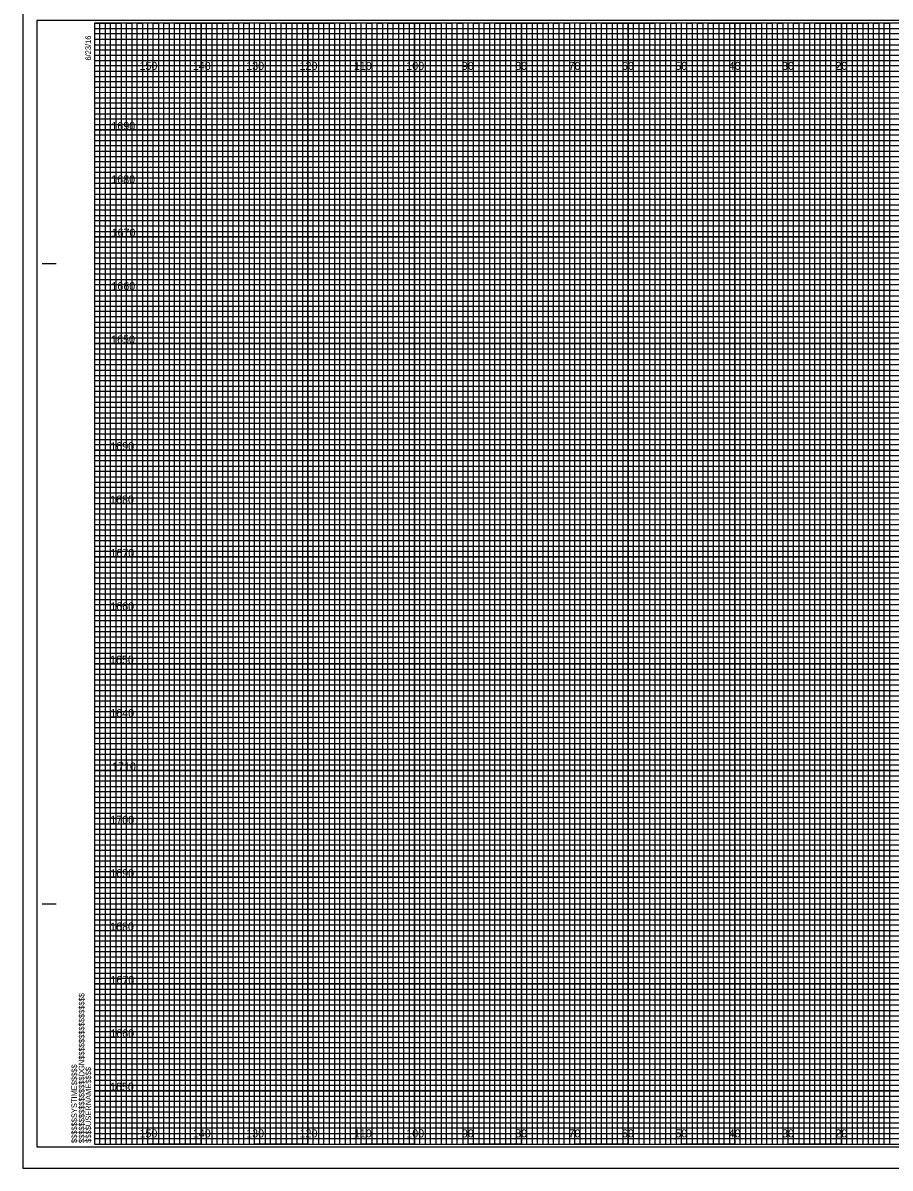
# Model space of a CAD drawing. Extents: x 1443 to 2205, y -29 to 5484.
# Drawn here: x 1443.3 to 1605.8, y 645.2 to 859.8 of the extents above; entities that cross this region are included whole.
import ezdxf

# ---------------------------------------------------------------- set-up
doc = ezdxf.new("R2010")
doc.units = 0
for name, color, linetype in [('Pattern 3', 7, 'Continuous'), ('Prop Retaining Wall', 7, 'Continuous'), ('Prop XS DDE Earthwork Shape', 7, 'Continuous'), ('Prop XS DDE Slope Text', 7, 'Continuous'), ('Prop XS DDE Text', 7, 'Continuous'), ('Prop XS Earthwork Shape', 7, 'Continuous'), ('Prop XS Retaining Wall', 7, 'Continuous'), ('Prop XS Station Labels', 7, 'Continuous'), ('Prop XS Temporary Shoring', 7, 'Continuous'), ('Raster_Level_0', 7, 'Continuous'), ('Scratch_Level_3', 7, 'Continuous')]:
    doc.layers.add(name, color=color, linetype=linetype)

msp = doc.modelspace()

# ---------------------------------------------------------------- linework, layer by layer
at = {"layer": 'Pattern 3'}
for p, q in [((1443.28, 864.21), (1443.28, 645.21)), ((1443.28, 645.21), (1779.98, 645.21))]:
    msp.add_line(p, q, dxfattribs=at)
at = {"layer": 'Prop Retaining Wall'}
for p, q in [((1456.68, 858.71), (1716.68, 858.71)), ((1716.68, 857.69), (1456.68, 857.69)), ((1456.68, 857.69), (1456.68, 856.71)), ((1456.68, 856.71), (1716.68, 856.71)), ((1716.68, 855.6), (1456.68, 855.6)), ((1456.68, 855.6), (1456.68, 853.71)), ((1456.68, 853.71), (1776.68, 853.71))]:
    msp.add_line(p, q, dxfattribs=at)
for points in [[(1456.68, 852.71), (1726.68, 852.71), (1776.68, 852.71), (1776.68, 851.71), (1456.68, 851.71)], [(1456.68, 850.71), (1776.68, 850.71), (1776.68, 848.71), (1456.68, 848.71)], [(1456.68, 847.71), (1776.68, 847.71), (1776.68, 846.71), (1456.68, 846.69)], [(1456.68, 845.71), (1776.68, 845.71), (1776.68, 843.71), (1456.68, 843.71)], [(1456.68, 842.71), (1776.68, 842.71), (1776.68, 841.71), (1456.68, 841.71)], [(1456.68, 840.71), (1776.68, 840.71), (1776.68, 838.71), (1456.68, 838.71)], [(1456.68, 837.71), (1776.68, 837.71), (1776.68, 836.71), (1456.68, 836.71)], [(1456.68, 835.71), (1776.68, 835.71), (1776.68, 833.71), (1456.68, 833.71)], [(1456.68, 832.71), (1776.68, 832.71), (1776.68, 831.71), (1456.68, 831.71)], [(1456.68, 830.71), (1776.68, 830.71), (1776.68, 828.71), (1456.68, 828.71)], [(1456.68, 827.71), (1776.68, 827.71), (1776.68, 826.71), (1456.68, 826.71)], [(1456.68, 825.71), (1776.68, 825.71), (1776.68, 823.66), (1776.68, 822.71), (1776.68, 821.71), (1456.68, 821.71)], [(1456.68, 823.71), (1776.68, 823.71), (1776.68, 822.71), (1456.68, 822.71)], [(1456.68, 820.71), (1776.68, 820.71), (1776.68, 818.71), (1456.68, 818.74)], [(1456.68, 818.74), (1776.68, 818.71), (1776.68, 817.71), (1456.68, 817.71)], [(1456.68, 816.71), (1776.68, 816.71), (1776.68, 815.71), (1456.68, 815.71)], [(1456.68, 813.71), (1776.68, 813.71), (1776.68, 812.71), (1456.68, 812.71)], [(1456.68, 811.71), (1776.68, 811.71), (1776.68, 810.71), (1456.68, 810.71)], [(1456.61, 808.6), (1776.68, 808.6), (1776.68, 807.59), (1456.61, 807.59)], [(1456.68, 806.71), (1776.68, 806.71), (1776.68, 805.71), (1456.68, 805.71)], [(1456.68, 803.71), (1776.68, 803.71), (1776.68, 802.71), (1456.68, 802.71)], [(1456.68, 801.71), (1776.68, 801.71), (1776.68, 800.71), (1456.68, 800.71)], [(1456.68, 798.71), (1776.68, 798.71), (1776.68, 797.71), (1456.68, 797.71)], [(1456.68, 796.71), (1776.68, 796.71), (1776.68, 795.71), (1456.68, 795.71)], [(1456.68, 793.71), (1776.68, 793.71), (1776.68, 792.71), (1456.68, 792.71)], [(1456.68, 791.71), (1776.68, 791.71), (1776.68, 790.71), (1456.68, 790.71)], [(1456.68, 788.71), (1776.68, 788.71), (1776.67, 787.69), (1456.68, 787.71)], [(1456.68, 786.71), (1776.68, 786.71), (1776.68, 785.71), (1456.68, 785.71)], [(1456.68, 783.71), (1776.68, 783.71), (1776.68, 782.71), (1456.68, 782.71)], [(1456.68, 781.71), (1776.68, 781.71), (1776.68, 780.71), (1456.68, 780.71)], [(1456.68, 778.71), (1776.68, 778.71), (1776.68, 777.71), (1456.68, 777.71)], [(1456.68, 776.71), (1776.68, 776.71), (1776.68, 775.71), (1456.68, 775.71)], [(1456.68, 773.71), (1776.68, 773.71), (1776.68, 772.71), (1456.68, 772.71)], [(1456.68, 771.71), (1776.68, 771.71), (1776.68, 770.71), (1456.68, 770.71)], [(1456.68, 768.71), (1776.68, 768.71), (1776.68, 767.71), (1456.68, 767.71)], [(1456.68, 766.7), (1776.75, 766.62), (1776.68, 765.71), (1456.68, 765.71)], [(1456.68, 763.71), (1776.68, 763.71), (1776.68, 762.71), (1456.68, 762.71)], [(1456.68, 761.71), (1776.68, 761.71), (1776.68, 760.71), (1456.68, 760.71)], [(1456.68, 758.71), (1776.68, 758.71), (1776.68, 757.71), (1456.68, 757.71)], [(1456.68, 756.71), (1776.68, 756.71), (1776.68, 755.71), (1456.68, 755.71)], [(1456.68, 753.71), (1776.68, 753.71), (1776.68, 752.71), (1456.68, 752.71)], [(1456.68, 751.71), (1776.68, 751.71), (1776.68, 750.71), (1456.68, 750.71)], [(1456.68, 748.71), (1776.68, 748.71), (1776.68, 747.71), (1456.68, 747.71)], [(1456.68, 746.71), (1776.68, 746.71), (1776.68, 745.71), (1456.68, 745.71)], [(1456.68, 743.71), (1776.68, 743.71), (1776.68, 742.71), (1456.68, 742.71)], [(1456.68, 741.71), (1776.68, 741.71), (1776.68, 740.71), (1456.68, 740.71)], [(1456.68, 738.71), (1776.68, 738.71), (1776.68, 737.71), (1456.68, 737.71)], [(1456.68, 736.71), (1776.68, 736.71), (1776.68, 735.71), (1456.68, 735.71)], [(1456.68, 733.71), (1776.68, 733.71), (1776.68, 732.71), (1456.68, 732.71)], [(1456.68, 731.71), (1776.68, 731.71), (1776.68, 730.71), (1456.68, 730.71)], [(1456.68, 728.71), (1776.68, 728.71), (1776.67, 727.69), (1456.68, 727.71)], [(1456.68, 726.71), (1776.68, 726.71), (1776.68, 725.71), (1456.68, 725.71)], [(1456.68, 723.71), (1776.68, 723.71), (1776.68, 722.71), (1456.68, 722.71)], [(1456.68, 721.71), (1776.68, 721.71), (1776.68, 720.71), (1456.68, 720.71)], [(1456.68, 718.71), (1776.68, 718.71), (1776.68, 717.71), (1456.68, 717.71)], [(1456.68, 716.71), (1776.68, 716.71), (1776.68, 715.71), (1456.68, 715.71)], [(1456.68, 713.71), (1776.68, 713.71), (1776.68, 712.71), (1456.68, 712.71)], [(1456.68, 711.71), (1776.68, 711.71), (1776.68, 710.71), (1456.68, 710.71)], [(1456.68, 708.71), (1776.68, 708.71), (1776.68, 707.71), (1456.68, 707.71)], [(1456.68, 706.7), (1776.75, 706.62), (1776.68, 705.71), (1456.68, 705.71)], [(1456.68, 703.71), (1776.68, 703.71), (1776.68, 702.71), (1456.68, 702.71)], [(1456.68, 701.71), (1776.68, 701.71), (1776.68, 700.71), (1456.68, 700.71)], [(1456.68, 698.71), (1776.68, 698.71), (1776.68, 697.71), (1456.68, 697.71)], [(1456.68, 696.71), (1776.68, 696.71), (1776.68, 695.71), (1456.68, 695.71)], [(1456.68, 693.71), (1776.68, 693.71), (1776.68, 692.71), (1456.68, 692.71)], [(1456.68, 691.71), (1776.68, 691.71), (1776.68, 690.71), (1456.68, 690.71)], [(1456.68, 688.71), (1776.68, 688.71), (1776.68, 687.71), (1456.68, 687.71)], [(1456.68, 686.71), (1776.68, 686.71), (1776.68, 685.71), (1456.68, 685.71)], [(1456.68, 683.71), (1776.68, 683.71), (1776.68, 682.71), (1456.68, 682.71)], [(1456.68, 681.71), (1776.68, 681.71), (1776.68, 680.71), (1456.68, 680.71)], [(1456.68, 678.71), (1776.68, 678.71), (1776.68, 677.71), (1456.68, 677.71)], [(1456.68, 676.71), (1776.68, 676.71), (1776.68, 675.71), (1456.68, 675.71)], [(1456.68, 673.71), (1776.68, 673.71), (1776.68, 672.71), (1456.68, 672.71)], [(1456.68, 671.71), (1776.68, 671.71), (1776.68, 670.71), (1456.68, 670.71)], [(1456.68, 668.71), (1776.68, 668.71), (1776.68, 667.71), (1456.68, 667.71)], [(1456.68, 666.71), (1776.68, 666.71), (1776.68, 665.71), (1456.68, 665.71)], [(1456.68, 663.71), (1776.68, 663.71), (1776.68, 662.71), (1456.68, 662.71)], [(1456.68, 661.71), (1776.68, 661.71), (1776.68, 660.71), (1456.68, 660.71)], [(1456.68, 658.71), (1776.68, 658.71), (1776.68, 657.71), (1456.68, 657.71)], [(1456.68, 656.71), (1776.68, 656.71), (1776.68, 655.71), (1456.68, 655.71)], [(1456.68, 653.71), (1776.68, 653.71), (1776.68, 652.71), (1456.68, 652.71)], [(1456.68, 651.71), (1776.68, 651.71), (1776.68, 650.71), (1456.68, 650.71)]]:
    msp.add_lwpolyline(points, dxfattribs=at)
at = {"layer": 'Prop XS DDE Earthwork Shape'}
msp.add_lwpolyline([(1445.88, 649.21), (1779.08, 649.21), (1779.08, 860.21), (1445.88, 860.21)], close=True, dxfattribs=at)
at = {"layer": 'Prop XS DDE Slope Text'}
for points in [[(1456.68, 649.71), (1457.68, 649.71), (1457.68, 859.71), (1458.68, 859.71), (1458.68, 649.71)], [(1458.68, 649.71), (1459.68, 649.71), (1459.68, 859.71), (1460.68, 859.71), (1460.68, 649.71)], [(1461.68, 649.71), (1462.68, 649.71), (1462.68, 859.71), (1463.68, 859.71), (1463.68, 649.71)], [(1463.68, 649.71), (1464.68, 649.71), (1464.68, 859.71), (1465.68, 859.71), (1465.68, 649.71)], [(1466.68, 649.71), (1467.68, 649.71), (1467.68, 859.71), (1468.68, 859.71), (1468.68, 649.71)], [(1468.68, 649.71), (1469.68, 649.71), (1469.68, 859.71), (1470.68, 859.71), (1470.68, 649.71)], [(1471.68, 649.71), (1472.68, 649.71), (1472.68, 859.71), (1473.68, 859.71), (1473.68, 649.71)], [(1473.68, 649.71), (1474.68, 649.71), (1474.68, 859.71), (1475.68, 859.71), (1475.68, 649.71)], [(1476.68, 649.71), (1477.68, 649.71), (1477.68, 859.71), (1478.68, 859.71), (1478.68, 649.71)], [(1478.68, 649.71), (1479.68, 649.71), (1479.68, 859.71), (1480.68, 859.71), (1480.68, 649.71)], [(1481.68, 649.71), (1482.68, 649.71), (1482.68, 859.71), (1483.68, 859.71), (1483.68, 649.71)], [(1483.68, 649.71), (1484.68, 649.71), (1484.68, 859.71), (1485.68, 859.71), (1485.68, 649.71)], [(1486.68, 649.71), (1487.68, 649.71), (1487.68, 859.71), (1488.68, 859.71), (1488.68, 649.71)], [(1488.68, 649.71), (1489.68, 649.71), (1489.68, 859.71), (1490.68, 859.71), (1490.68, 649.71)], [(1491.68, 649.71), (1492.68, 649.71), (1492.68, 859.71), (1493.68, 859.71), (1493.68, 649.71)], [(1493.68, 649.71), (1494.68, 649.71), (1494.68, 859.71), (1495.68, 859.71), (1495.68, 649.71)], [(1496.68, 649.71), (1497.68, 649.71), (1497.68, 859.71), (1498.68, 859.71), (1498.68, 649.71)], [(1498.68, 649.71), (1499.68, 649.71), (1499.68, 859.71), (1500.68, 859.71), (1500.68, 649.71)], [(1501.68, 649.71), (1502.68, 649.71), (1502.68, 859.71), (1503.68, 859.71), (1503.68, 649.71)], [(1503.68, 649.71), (1504.68, 649.71), (1504.68, 859.71), (1505.68, 859.71), (1505.68, 649.71)], [(1506.68, 649.71), (1507.68, 649.71), (1507.68, 859.71), (1508.68, 859.71), (1508.68, 649.71)], [(1508.68, 649.71), (1509.68, 649.71), (1509.68, 859.71), (1510.68, 859.71), (1510.68, 649.71)], [(1511.68, 649.71), (1512.68, 649.71), (1512.68, 859.71), (1513.68, 859.71), (1513.68, 649.71)], [(1513.68, 649.71), (1514.68, 649.71), (1514.68, 859.71), (1515.68, 859.71), (1515.68, 649.71)], [(1516.68, 649.71), (1517.68, 649.71), (1517.68, 859.71), (1518.68, 859.71), (1518.68, 649.71)], [(1518.68, 649.71), (1519.68, 649.71), (1519.68, 859.71), (1520.68, 859.71), (1520.68, 649.71)], [(1521.68, 649.71), (1522.68, 649.71), (1522.68, 859.71), (1523.68, 859.71), (1523.68, 649.71)], [(1523.68, 649.71), (1524.68, 649.71), (1524.68, 859.71), (1525.68, 859.71), (1525.68, 649.71)], [(1526.68, 649.71), (1527.68, 649.71), (1527.68, 859.71), (1528.68, 859.71), (1528.68, 649.71)], [(1528.68, 649.71), (1529.68, 649.71), (1529.68, 859.71), (1530.68, 859.71), (1530.68, 649.71)], [(1531.68, 649.71), (1532.68, 649.71), (1532.68, 859.71), (1533.68, 859.71), (1533.68, 649.71)], [(1533.68, 649.71), (1534.68, 649.71), (1534.68, 859.71), (1535.68, 859.71), (1535.68, 649.71)], [(1536.68, 649.71), (1537.68, 649.71), (1537.68, 859.71), (1538.68, 859.71), (1538.68, 649.71)], [(1538.68, 649.71), (1539.68, 649.71), (1539.68, 859.71), (1540.68, 859.71), (1540.68, 649.71)], [(1541.68, 649.71), (1542.68, 649.71), (1542.68, 859.71), (1543.68, 859.71), (1543.68, 649.71)], [(1543.68, 649.71), (1544.68, 649.71), (1544.68, 859.71), (1545.68, 859.71), (1545.68, 649.71)], [(1546.68, 649.71), (1547.68, 649.71), (1547.68, 859.71), (1548.68, 859.71), (1548.68, 649.71)], [(1548.68, 649.71), (1549.68, 649.71), (1549.68, 859.71), (1550.68, 859.71), (1550.68, 649.71)], [(1551.68, 649.71), (1552.68, 649.71), (1552.68, 859.71), (1553.68, 859.71), (1553.68, 649.71)], [(1553.68, 649.71), (1554.68, 649.71), (1554.68, 859.71), (1555.68, 859.71), (1555.68, 649.71)], [(1556.68, 649.71), (1557.68, 649.71), (1557.68, 859.71), (1558.68, 859.71), (1558.68, 649.71)], [(1558.68, 649.71), (1559.68, 649.71), (1559.68, 859.71), (1560.68, 859.71), (1560.68, 649.71)], [(1561.68, 649.71), (1562.68, 649.71), (1562.68, 859.71), (1563.68, 859.71), (1563.68, 649.71)], [(1563.68, 649.71), (1564.68, 649.71), (1564.68, 859.71), (1565.68, 859.71), (1565.68, 649.71)], [(1566.68, 649.71), (1567.68, 649.71), (1567.68, 859.71), (1568.68, 859.71), (1568.68, 649.71)], [(1568.68, 649.71), (1569.68, 649.71), (1569.68, 859.71), (1570.68, 859.71), (1570.68, 649.71)], [(1571.68, 649.71), (1572.68, 649.71), (1572.68, 859.71), (1573.68, 859.71), (1573.68, 649.71)], [(1573.68, 649.71), (1574.68, 649.71), (1574.68, 859.71), (1575.68, 859.71), (1575.68, 649.71)], [(1576.68, 649.71), (1577.68, 649.71), (1577.68, 859.71), (1578.68, 859.71), (1578.68, 649.71)], [(1578.68, 649.71), (1579.68, 649.71), (1579.68, 859.71), (1580.68, 859.71), (1580.68, 649.71)], [(1581.68, 649.71), (1582.68, 649.71), (1582.68, 859.71), (1583.68, 859.71), (1583.68, 649.71)], [(1583.68, 649.71), (1584.68, 649.71), (1584.68, 859.71), (1585.68, 859.71), (1585.68, 649.71)], [(1586.68, 649.71), (1587.68, 649.71), (1587.68, 859.71), (1588.68, 859.71), (1588.68, 649.71)], [(1588.68, 649.71), (1589.68, 649.71), (1589.68, 859.71), (1590.68, 859.71), (1590.68, 649.71)], [(1591.68, 649.71), (1592.68, 649.71), (1592.68, 859.71), (1593.68, 859.71), (1593.68, 649.71)], [(1593.68, 649.71), (1594.68, 649.71), (1594.68, 859.71), (1595.68, 859.71), (1595.68, 649.71)], [(1596.68, 649.71), (1597.68, 649.71), (1597.68, 859.71), (1598.68, 859.71), (1598.68, 649.71)], [(1598.68, 649.71), (1599.68, 649.71), (1599.68, 859.71), (1600.68, 859.71), (1600.68, 649.71)], [(1601.68, 649.71), (1602.68, 649.71), (1602.68, 859.71), (1603.68, 859.71), (1603.68, 649.71)], [(1603.68, 649.71), (1604.68, 649.71), (1604.68, 859.71), (1605.68, 859.71), (1605.68, 649.71)]]:
    msp.add_lwpolyline(points, dxfattribs=at)
at = {"layer": 'Prop XS DDE Text'}
msp.add_lwpolyline([(1443.28, 645.21), (1779.98, 645.21), (1779.98, 864.21), (1443.28, 864.21)], close=True, dxfattribs=at)
at = {"layer": 'Prop XS Earthwork Shape'}
for p, q in [((1466.68, 859.71), (1456.68, 859.71)), ((1466.68, 649.71), (1466.68, 859.71)), ((1486.68, 859.71), (1476.68, 859.71)), ((1476.68, 859.71), (1476.68, 649.71)), ((1486.68, 649.71), (1486.68, 859.71)), ((1506.68, 859.71), (1496.68, 859.71)), ((1496.68, 859.71), (1496.68, 649.71)), ((1506.68, 649.71), (1506.68, 859.71)), ((1526.68, 859.71), (1516.68, 859.71)), ((1516.68, 859.71), (1516.68, 649.71)), ((1526.68, 649.71), (1526.68, 859.71)), ((1546.68, 859.71), (1536.68, 859.71)), ((1536.68, 859.71), (1536.68, 649.71)), ((1546.68, 649.71), (1546.68, 859.71)), ((1566.68, 859.71), (1556.68, 859.71)), ((1556.68, 859.71), (1556.68, 649.71)), ((1566.68, 649.71), (1566.68, 859.71)), ((1586.68, 859.71), (1576.68, 859.71)), ((1576.68, 859.71), (1576.68, 649.71)), ((1586.68, 649.71), (1586.68, 859.71)), ((1606.68, 859.71), (1596.68, 859.71)), ((1596.68, 859.71), (1596.68, 649.71)), ((1476.68, 649.71), (1466.68, 649.71)), ((1496.68, 649.71), (1486.68, 649.71)), ((1516.68, 649.71), (1506.68, 649.71)), ((1536.68, 649.71), (1526.68, 649.71)), ((1556.68, 649.71), (1546.68, 649.71)), ((1576.68, 649.71), (1566.68, 649.71)), ((1596.68, 649.71), (1586.68, 649.71))]:
    msp.add_line(p, q, dxfattribs=at)
for points in [[(1456.68, 849.71), (1776.68, 849.71), (1776.68, 839.71), (1456.68, 839.71)], [(1456.68, 829.71), (1776.68, 829.71), (1776.68, 819.71), (1456.68, 819.71)], [(1456.68, 809.71), (1776.68, 809.71), (1776.68, 799.71), (1456.68, 799.71)], [(1456.68, 789.71), (1776.68, 789.71), (1776.68, 779.71), (1456.68, 779.71)], [(1456.68, 769.71), (1776.68, 769.71), (1776.68, 759.71), (1456.68, 759.71)], [(1456.68, 749.71), (1776.68, 749.71), (1776.68, 739.71), (1456.68, 739.71)], [(1456.68, 729.71), (1776.68, 729.71), (1776.68, 719.71), (1456.68, 719.71)], [(1456.68, 709.71), (1776.68, 709.71), (1776.68, 699.71), (1456.68, 699.71)], [(1456.68, 689.71), (1776.68, 689.71), (1776.68, 679.71), (1456.68, 679.71)], [(1456.68, 669.71), (1776.68, 669.71), (1776.68, 659.71), (1456.68, 659.71)]]:
    msp.add_lwpolyline(points, dxfattribs=at)
at = {"layer": 'Prop XS Retaining Wall'}
for p, q in [((1446.88, 814.71), (1449.38, 814.71)), ((1446.98, 814.71), (1449.48, 814.71)), ((1446.88, 694.71), (1449.38, 694.71)), ((1446.98, 694.71), (1449.48, 694.71)), ((1456.68, 649.71), (1456.68, 649.71)), ((1456.68, 649.71), (1456.68, 649.71)), ((1456.68, 649.71), (1456.68, 649.71)), ((1456.68, 649.71), (1456.68, 649.71)), ((1456.68, 649.71), (1456.68, 649.71)), ((1456.68, 649.71), (1456.68, 649.71)), ((1456.68, 649.71), (1456.68, 649.71))]:
    msp.add_line(p, q, dxfattribs=at)
msp.add_lwpolyline([(1776.68, 859.71), (1456.68, 859.71), (1456.68, 649.71), (1776.68, 649.71)], close=True, dxfattribs=at)
at = {"layer": 'Prop XS Station Labels'}
for points in [[(1456.68, 859.71), (1461.68, 859.71), (1461.68, 649.71), (1471.68, 649.71), (1471.68, 859.71), (1481.68, 859.71), (1481.68, 649.71), (1491.68, 649.71), (1491.68, 859.71), (1501.68, 859.71), (1501.68, 649.71), (1511.68, 649.71), (1511.68, 859.71), (1521.68, 859.71), (1521.68, 649.71), (1531.68, 649.71), (1531.68, 859.71), (1541.68, 859.71), (1541.68, 649.71), (1551.68, 649.71), (1551.68, 859.71), (1561.68, 859.71), (1561.68, 649.71), (1571.68, 649.71), (1571.68, 859.71), (1581.68, 859.71), (1581.68, 649.71), (1591.68, 649.71), (1591.68, 859.71), (1601.68, 859.71), (1601.68, 649.71), (1611.68, 649.71)], [(1456.68, 854.71), (1731.68, 854.71)], [(1456.68, 834.71), (1776.68, 834.71), (1776.68, 844.71), (1456.68, 844.71)], [(1456.68, 814.71), (1776.68, 814.71), (1776.68, 824.71), (1456.68, 824.71)], [(1456.68, 794.71), (1776.68, 794.71), (1776.68, 804.71), (1456.68, 804.71)], [(1456.68, 774.71), (1776.68, 774.71), (1776.68, 784.71), (1456.68, 784.71)], [(1456.68, 754.71), (1776.68, 754.71), (1776.68, 764.71), (1456.68, 764.71)], [(1456.68, 734.71), (1776.68, 734.71), (1776.68, 744.71), (1456.68, 744.71)], [(1456.68, 714.71), (1776.68, 714.71), (1776.68, 724.71), (1456.68, 724.71)], [(1456.68, 694.71), (1776.68, 694.71), (1776.68, 704.71), (1456.68, 704.71)], [(1456.68, 674.71), (1776.68, 674.71), (1776.68, 684.71), (1456.68, 684.71)], [(1456.68, 654.71), (1776.68, 654.71), (1776.68, 664.71), (1456.68, 664.71)]]:
    msp.add_lwpolyline(points, dxfattribs=at)
at = {"layer": 'Prop XS Temporary Shoring'}
for p, q in [((1466.68, 649.71), (1466.68, 859.71)), ((1476.68, 649.71), (1476.68, 859.71)), ((1486.68, 649.71), (1486.68, 859.71)), ((1496.68, 649.71), (1496.68, 859.71)), ((1506.68, 649.71), (1506.68, 859.71)), ((1516.68, 649.71), (1516.68, 859.71)), ((1526.68, 649.71), (1526.68, 859.71)), ((1536.68, 649.71), (1536.68, 859.71)), ((1546.68, 649.71), (1546.68, 859.71)), ((1556.68, 649.71), (1556.68, 859.71)), ((1566.68, 649.71), (1566.68, 859.71)), ((1576.68, 649.71), (1576.68, 859.71)), ((1586.68, 649.71), (1586.68, 859.71)), ((1596.68, 649.71), (1596.68, 859.71)), ((1456.68, 849.71), (1776.68, 849.71)), ((1456.68, 839.71), (1776.68, 839.71)), ((1456.68, 829.71), (1776.68, 829.71)), ((1456.68, 819.71), (1776.68, 819.71)), ((1456.68, 809.71), (1776.68, 809.71)), ((1456.68, 799.71), (1776.68, 799.71)), ((1456.68, 789.71), (1776.68, 789.71)), ((1456.68, 779.71), (1776.68, 779.71)), ((1456.68, 769.71), (1776.68, 769.71)), ((1456.68, 759.71), (1776.68, 759.71)), ((1456.68, 749.71), (1776.68, 749.71)), ((1456.68, 739.71), (1776.68, 739.71)), ((1456.68, 729.71), (1776.68, 729.71)), ((1456.68, 719.71), (1776.68, 719.71)), ((1456.68, 709.71), (1776.68, 709.71)), ((1456.68, 699.71), (1776.68, 699.71)), ((1456.68, 689.71), (1776.68, 689.71)), ((1456.68, 679.71), (1776.68, 679.71)), ((1456.68, 669.71), (1776.68, 669.71)), ((1456.68, 659.71), (1776.68, 659.71))]:
    msp.add_line(p, q, dxfattribs=at)

# ---------------------------------------------------------------- texts
at = {"layer": 'Prop XS Retaining Wall'}
for s, p in [('6/23/16', (1456.03, 852.71)), ('$$$$$$$$$$$$$$$$DGN$$$$$$$$$$$$$$$$', (1454.8, 649.89)), ('$$$$$$SYSTIME$$$$$', (1453.42, 649.89)), ('$$$$USERNAME$$$$', (1456.06, 649.94))]:
    msp.add_text(s, height=1.05, rotation=90, dxfattribs=at).set_placement(p)
at = {"layer": 'Raster_Level_0'}
for s, p in [('150', (1465.12, 850.96)), ('140', (1475.12, 850.96)), ('130', (1485.12, 850.96)), ('120', (1495.12, 850.96)), ('110', (1505.3, 850.96)), ('100', (1515.12, 850.96)), ('90', (1525.53, 850.96)), ('80', (1535.53, 850.96)), ('70', (1545.53, 850.96)), ('60', (1555.53, 850.96)), ('50', (1565.53, 850.96)), ('40', (1575.53, 850.96)), ('30', (1585.53, 850.96)), ('20', (1595.53, 850.96)), ('150', (1465.12, 650.96)), ('140', (1475.12, 650.96)), ('130', (1485.12, 650.96)), ('120', (1495.12, 650.96)), ('110', (1505.3, 650.96)), ('100', (1515.12, 650.96)), ('90', (1525.53, 650.96)), ('80', (1535.53, 650.96)), ('70', (1545.53, 650.96)), ('60', (1555.53, 650.96)), ('50', (1565.53, 650.96)), ('40', (1575.53, 650.96)), ('30', (1585.53, 650.96)), ('20', (1595.53, 650.96))]:
    msp.add_text(s, height=1.5, dxfattribs=at).set_placement(p)
at = {"layer": 'Scratch_Level_3'}
for s, p in [('1690', (1459.86, 839.71)), ('1680', (1459.84, 829.71)), ('1670', (1459.9, 819.71)), ('1660', (1459.86, 809.71)), ('1650', (1459.81, 799.71)), ('1690', (1459.65, 779.71)), ('1680', (1459.62, 769.71)), ('1670', (1459.68, 759.71)), ('1660', (1459.65, 749.71)), ('1650', (1459.6, 739.71)), ('1640', (1459.65, 729.71)), ('1710', (1459.99, 719.71)), ('1700', (1459.66, 709.71)), ('1690', (1459.65, 699.71)), ('1680', (1459.62, 689.71)), ('1670', (1459.68, 679.71)), ('1660', (1459.65, 669.71)), ('1650', (1459.6, 659.71))]:
    msp.add_text(s, height=1.5, dxfattribs=at).set_placement(p)

doc.saveas('drawing.dxf')
